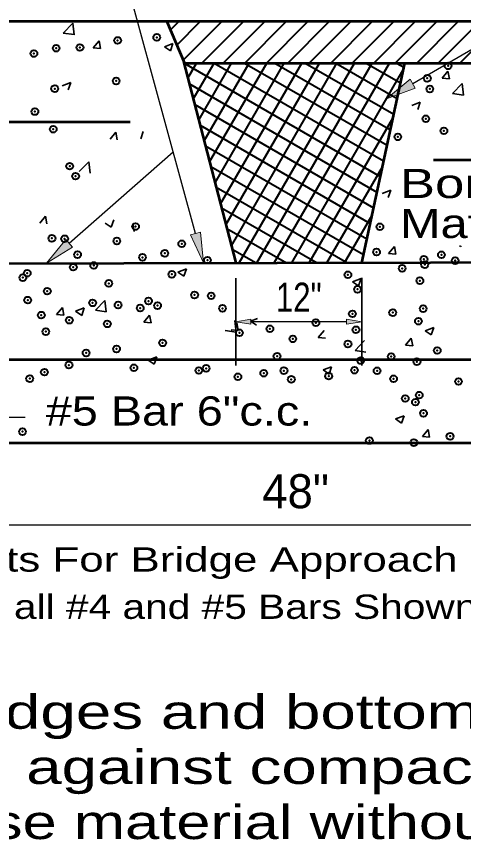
# Model space of a CAD drawing. Extents: x 36.4 to 71.7, y 0.5 to 22.5.
# Drawn here: x 46.897 to 48.735, y 6.743 to 10.127 of the extents above; entities that cross this region are included whole.
import ezdxf

# ---------------------------------------------------------------- set-up
doc = ezdxf.new("R2010")
doc.units = 0
doc.header["$LTSCALE"] = 0.056
doc.header["$PDMODE"] = 32
doc.header["$PDSIZE"] = 0.028
for name, color, linetype, lineweight in [('1', 7, 'Continuous', 40), ('3', 7, 'Continuous', 13), ('6', 7, 'Continuous', 13)]:
    doc.layers.add(name, color=color, linetype=linetype, lineweight=lineweight)

msp = doc.modelspace()

# ---------------------------------------------------------------- hatches: boundary and pattern name
at = {"layer": '1'}
for points in [[(47.86117, 8.86158), (47.86117, 8.88242), (47.79867, 8.872), (47.79867, 8.872)], [(48.25425, 8.86158), (48.25425, 8.88242), (48.31675, 8.872), (48.31675, 8.872)]]:
    msp.add_hatch(color=256, dxfattribs=at).paths.add_polyline_path(points)
at = {"layer": '3'}
for points in [[(48.53658, 9.83267), (48.51558, 9.86858), (48.41808, 9.78783), (48.41808, 9.78783)], [(47.65308, 9.23942), (47.61283, 9.2285), (47.66592, 9.11342), (47.66592, 9.11342)], [(47.12742, 9.17892), (47.09992, 9.21025), (47.01983, 9.11208), (47.01983, 9.11208)]]:
    msp.add_hatch(color=256, dxfattribs=at).paths.add_polyline_path(points)

# ---------------------------------------------------------------- linework, layer by layer
at = {"layer": '1', "lineweight": 35}
for p, q in [((47.089, 10.05883), (47.128, 10.09942)), ((47.1335, 10.05192), (47.128, 10.09942)), ((47.089, 10.05883), (47.1335, 10.052)), ((47.21225, 9.99808), (47.23633, 10.02683)), ((47.24217, 9.9955), (47.23633, 10.02683)), ((47.50517, 10.00258), (47.54017, 10.01608)), ((47.53008, 9.98583), (47.54017, 10.01608)), ((47.21225, 9.99808), (47.24217, 9.9955)), ((47.50517, 10.00258), (47.53008, 9.98583)), ((47.57083, 9.96675), (47.57317, 9.96942)), ((47.57083, 9.96675), (47.57442, 9.96642)), ((48.64675, 9.87258), (48.67083, 9.90133)), ((48.67667, 9.87), (48.67083, 9.90133)), ((47.08508, 9.84133), (47.12008, 9.85475)), ((47.10992, 9.82458), (47.12008, 9.85475)), ((48.64675, 9.87258), (48.67667, 9.87)), ((48.68992, 9.81058), (48.72883, 9.85117)), ((48.73433, 9.80367), (48.72883, 9.85117)), ((48.68992, 9.81058), (48.73433, 9.80367)), ((48.52217, 9.76125), (48.55717, 9.77467)), ((48.54708, 9.7445), (48.55725, 9.77467)), ((47.28158, 9.622), (47.30575, 9.65075)), ((47.3115, 9.61942), (47.30575, 9.65075)), ((47.40842, 9.62325), (47.4185, 9.6535)), ((47.15533, 9.48908), (47.19425, 9.52967)), ((47.15533, 9.48908), (47.19425, 9.52967)), ((47.19983, 9.48217), (47.19425, 9.52958)), ((48.4005, 9.39867), (48.43558, 9.41208)), ((48.42542, 9.38192), (48.43558, 9.41208)), ((46.99233, 9.27725), (47.0165, 9.306)), ((47.02225, 9.27467), (47.0165, 9.306)), ((47.26183, 9.2775), (47.28675, 9.26067)), ((47.28675, 9.26067), (47.29692, 9.29092)), ((47.38092, 9.24325), (47.37508, 9.27458)), ((48.42692, 9.15175), (48.451, 9.1805)), ((48.45675, 9.14917), (48.451, 9.1805)), ((48.71817, 9.18442), (48.72383, 9.18058)), ((48.72383, 9.18058), (48.72517, 9.18442)), ((48.42692, 9.15175), (48.45675, 9.14917)), ((47.56033, 9.07617), (47.59533, 9.08958)), ((47.56033, 9.07617), (47.58517, 9.05942)), ((47.58517, 9.05933), (47.59533, 9.08958)), ((47.79867, 9.05125), (47.79867, 8.692)), ((48.27892, 9.03608), (48.31392, 9.04958)), ((48.27892, 9.03608), (48.30375, 9.01933)), ((48.30375, 9.01933), (48.31392, 9.0495)), ((48.31675, 9.05233), (48.31675, 8.692)), ((47.22158, 8.91925), (47.26058, 8.95983)), ((47.26608, 8.91233), (47.26058, 8.95983)), ((47.06175, 8.90117), (47.08583, 8.92992)), ((47.06175, 8.90117), (47.09158, 8.89858)), ((47.09167, 8.89858), (47.08583, 8.92992)), ((47.14017, 8.91492), (47.17525, 8.92833)), ((47.14017, 8.91492), (47.16508, 8.89808)), ((47.16508, 8.89808), (47.17525, 8.92833)), ((47.22158, 8.91925), (47.26608, 8.91233)), ((47.42033, 8.86983), (47.4445, 8.8985)), ((47.42033, 8.86983), (47.45025, 8.86717)), ((47.45025, 8.86717), (47.4445, 8.8985)), ((47.79967, 8.82958), (47.79417, 8.87708)), ((47.80892, 8.83583), (47.80308, 8.86717)), ((47.85875, 8.87483), (47.8875, 8.88583)), ((47.85875, 8.87483), (47.88367, 8.85808)), ((47.75525, 8.8365), (47.79967, 8.82958)), ((47.779, 8.83842), (47.80892, 8.83583)), ((48.13767, 8.80708), (48.16175, 8.83575)), ((48.57733, 8.83483), (48.61233, 8.84825)), ((48.57733, 8.83483), (48.60217, 8.818)), ((48.60225, 8.818), (48.61233, 8.84825)), ((48.13767, 8.80708), (48.1675, 8.80442)), ((48.49625, 8.77567), (48.52033, 8.80442)), ((48.52617, 8.77308), (48.52033, 8.80442)), ((48.28883, 8.75367), (48.32783, 8.79433)), ((48.49625, 8.77567), (48.52617, 8.77308)), ((48.28883, 8.75367), (48.33333, 8.74683)), ((47.43867, 8.71358), (47.47367, 8.727)), ((47.43867, 8.71358), (47.4635, 8.69683)), ((47.4635, 8.69683), (47.47367, 8.727)), ((48.15725, 8.6735), (48.19225, 8.687)), ((48.15725, 8.6735), (48.18208, 8.65675)), ((48.18208, 8.65675), (48.19225, 8.687)), ((48.45567, 8.47225), (48.49067, 8.48567)), ((48.45567, 8.47225), (48.48058, 8.45542)), ((48.48058, 8.45542), (48.49067, 8.48567)), ((48.56567, 8.39958), (48.58975, 8.42833)), ((48.5955, 8.39692), (48.58975, 8.42833)), ((48.56567, 8.39958), (48.5955, 8.397))]:
    msp.add_line(p, q, dxfattribs=at)
at = {"layer": '1', "lineweight": 53}
for p, q in [((53.64358, 10.10608), (47.51525, 10.10608)), ((47.51525, 10.10608), (47.58758, 9.9355)), ((47.5825, 9.94733), (47.79867, 9.11375)), ((47.58758, 9.9355), (53.64358, 9.9355)), ((48.3165, 9.11375), (48.493, 9.9355)), ((47.36392, 9.69192), (43.57042, 9.69192)), ((52.62333, 9.53608), (48.61192, 9.53608)), ((49.75083, 8.71517), (46.304, 8.71517)), ((50.03808, 8.37225), (46.07633, 8.37225))]:
    msp.add_line(p, q, dxfattribs=at)
at = {"layer": '1'}
for p, q in [((47.52992, 10.0715), (47.5645, 10.10608)), ((47.55625, 10.00942), (47.65283, 10.10608)), ((47.5825, 9.94733), (47.74125, 10.10608)), ((47.65908, 9.9355), (47.82967, 10.10608)), ((47.74742, 9.9355), (47.918, 10.10608)), ((47.83583, 9.9355), (48.00642, 10.10608)), ((47.92425, 9.9355), (48.09483, 10.10608)), ((48.01258, 9.9355), (48.18317, 10.10608)), ((48.101, 9.9355), (48.27158, 10.10608)), ((48.18942, 9.9355), (48.36, 10.10608)), ((48.27775, 9.9355), (48.44833, 10.10608)), ((48.36617, 9.9355), (48.53675, 10.10608)), ((48.45458, 9.9355), (48.62517, 10.10608)), ((48.54292, 9.9355), (48.7135, 10.10608)), ((48.63133, 9.9355), (48.80192, 10.10608)), ((48.71975, 9.9355), (48.89033, 10.10608)), ((47.58583, 9.93467), (48.39275, 9.46883)), ((47.60158, 9.87375), (47.63725, 9.9355)), ((47.624, 9.78742), (47.70942, 9.9355)), ((47.64633, 9.70117), (47.78158, 9.9355)), ((47.66867, 9.61492), (47.85375, 9.9355)), ((47.69108, 9.52867), (47.92592, 9.9355)), ((47.7095, 9.9355), (48.40658, 9.533)), ((47.71342, 9.44242), (47.99808, 9.9355)), ((47.73583, 9.35617), (48.07025, 9.9355)), ((47.75817, 9.26983), (48.14242, 9.9355)), ((47.7805, 9.18358), (48.21458, 9.9355)), ((47.81233, 9.11375), (48.28675, 9.9355)), ((47.8345, 9.9355), (48.42033, 9.59725)), ((47.8845, 9.11375), (48.35892, 9.9355)), ((47.95667, 9.11375), (48.43108, 9.9355)), ((47.9595, 9.9355), (48.43417, 9.66142)), ((48.0845, 9.9355), (48.44792, 9.72558)), ((48.2095, 9.9355), (48.46175, 9.78983)), ((48.3345, 9.9355), (48.4755, 9.854)), ((48.4595, 9.9355), (48.48933, 9.91825)), ((48.02883, 9.11375), (48.48692, 9.90717)), ((47.60783, 9.84983), (48.379, 9.40458)), ((47.62983, 9.765), (48.36517, 9.34042)), ((47.65183, 9.68008), (48.35142, 9.27617)), ((48.101, 9.11375), (48.44417, 9.70808)), ((47.67383, 9.59525), (48.33758, 9.212)), ((47.69583, 9.51033), (48.32383, 9.14775)), ((48.17317, 9.11375), (48.40142, 9.509)), ((47.71783, 9.4255), (48.25775, 9.11375)), ((47.73983, 9.34058), (48.13275, 9.11375)), ((48.24533, 9.11375), (48.35867, 9.30992)), ((47.76183, 9.25575), (48.00775, 9.11375)), ((47.78383, 9.17083), (47.88275, 9.11375))]:
    msp.add_line(p, q, dxfattribs=at)
at = {"layer": '1', "lineweight": 25}
for p, q in [((48.25425, 8.872), (47.86117, 8.872)), ((49.91308, 8.03517), (46.20133, 8.03517))]:
    msp.add_line(p, q, dxfattribs=at)
at = {"layer": '1', "lineweight": 53}
msp.add_lwpolyline([(47.51525, 10.10608), (43.59017, 10.10608), (43.59017, 9.827), (43.43175, 9.55683), (43.67933, 9.42175), (43.62983, 9.27633), (44.10525, 9.27633), (46.07633, 9.11), (53.64175, 9.12625)], dxfattribs=at)
at = {"layer": '1', "lineweight": 13}
for points in [[(47.86117, 8.86158), (47.86117, 8.88242), (47.79867, 8.872), (47.79867, 8.872)], [(48.25425, 8.86158), (48.25425, 8.88242), (48.31675, 8.872), (48.31675, 8.872)]]:
    msp.add_lwpolyline(points, close=True, dxfattribs=at)
at = {"layer": '1'}
for p in [(47.47367, 10.04083), (47.31283, 10.02817), (46.9685, 9.97433), (47.06025, 9.99617), (47.15792, 9.99925), (48.6715, 9.92358), (48.586, 9.87275), (47.30675, 9.86175), (47.05417, 9.82975), (48.59642, 9.82892), (46.97267, 9.73575), (48.57992, 9.70625), (47.04808, 9.66333), (48.46483, 9.63167), (48.65425, 9.65658), (47.11567, 9.51133), (47.14017, 9.47033), (47.38658, 9.26308), (48.39117, 9.26217), (47.04275, 9.21483), (47.095, 9.213), (47.30967, 9.20358), (47.57658, 9.19225), (48.37733, 9.15842), (47.14817, 9.14767), (47.41508, 9.13642), (47.50642, 9.15325), (47.682, 9.12508), (48.57217, 9.1285), (48.64425, 9.14717), (48.70058, 9.12308), (47.1305, 9.09625), (47.21483, 9.10325), (48.48275, 9.09125), (48.57542, 9.10658), (46.94117, 9.07133), (47.536, 9.067), (48.25958, 9.065), (46.92325, 9.05317), (47.27633, 9.0295), (48.55558, 9.0405), (47.02375, 8.9975), (48.29892, 9.00525), (46.94325, 8.96067), (47.43992, 8.95708), (47.62933, 8.982), (47.69733, 8.97833), (47.21017, 8.94942), (47.31475, 8.94058), (47.40575, 8.92825), (47.47708, 8.93808), (47.744, 8.92683), (48.569, 8.92583), (46.999, 8.899), (48.27783, 8.90425), (48.44383, 8.90933), (47.11417, 8.87817), (47.27025, 8.86308), (48.12808, 8.86775), (48.5495, 8.874), (47.01767, 8.83108), (47.81358, 8.82642), (47.93875, 8.84283), (48.29283, 8.83883), (47.49775, 8.78483), (48.03308, 8.80133), (47.30842, 8.75992), (48.25992, 8.78008), (48.62683, 8.75358), (47.18325, 8.74342), (47.96833, 8.73), (48.4375, 8.72867), (47.11283, 8.69392), (47.37975, 8.68258), (48.31233, 8.71217), (48.54342, 8.70758), (47.01158, 8.66458), (47.64667, 8.67133), (47.67675, 8.68), (47.91358, 8.66008), (47.99658, 8.67058), (48.1805, 8.64875), (48.28675, 8.67242), (48.37967, 8.67033), (46.95133, 8.638), (47.80717, 8.64567), (48.027, 8.63492), (48.44742, 8.6375), (48.71433, 8.62625), (48.49533, 8.55633), (48.55283, 8.57033), (48.53733, 8.54117), (48.57067, 8.49533), (46.92175, 8.42), (48.34792, 8.38333), (48.67958, 8.40075), (48.53125, 8.37467)]:
    msp.add_point(p, dxfattribs=at)
at = {"layer": '3', "lineweight": 25}
for p, q in [((48.52608, 9.85067), (50.90675, 11.2355)), ((47.11375, 9.19458), (47.54125, 9.57008))]:
    msp.add_line(p, q, dxfattribs=at)
for points in [[(47.633, 9.234), (47.23175, 10.70433), (46.89858, 10.70433)], [(46.52567, 8.63), (46.68658, 8.48008), (46.93275, 8.48008)]]:
    msp.add_lwpolyline(points, dxfattribs=at)
at = {"layer": '3'}
for points in [[(48.53658, 9.83267), (48.51558, 9.86858), (48.41808, 9.78783), (48.41808, 9.78783)], [(47.65308, 9.23942), (47.61283, 9.2285), (47.66592, 9.11342), (47.66592, 9.11342)], [(47.12742, 9.17892), (47.09992, 9.21025), (47.01983, 9.11208), (47.01983, 9.11208)]]:
    msp.add_lwpolyline(points, close=True, dxfattribs=at)
at = {"layer": '6'}
for p, q in [((47.51525, 10.10608), (47.51533, 10.10608)), ((47.51525, 10.10608), (47.51533, 10.10608)), ((47.79867, 9.11375), (47.79875, 9.11375)), ((48.31675, 9.11483), (48.31683, 9.11483)), ((47.79867, 8.872), (47.79875, 8.872))]:
    msp.add_line(p, q, dxfattribs=at)

# ---------------------------------------------------------------- texts
at = {"layer": '1'}
msp.add_text('48"', height=0.14, dxfattribs=at).set_placement((47.90725, 8.10517))
at = {"layer": '3'}
for s, height, width, p in [('Bond Breaking', 0.12, 1.35, (48.47325, 9.38017)), ('Material', 0.12, 1.25, (48.47325, 9.21592)), ('12"', 0.12, 0.8, (47.96342, 8.91258)), ('#5 Bar 6"c.c.', 0.12, 1.2, (47.01725, 8.445)), ('Pay Limits For Bridge Approach Expansion Joint', 0.1, 1.35, (46.16208, 7.84458)), ('(Includes all #4 and #5 Bars Shown above)', 0.1, 1.25, (46.16208, 7.65033)), ('Outside edges and bottom of subslab', 0.14, 1.4, (45.72758, 7.1985)), ('to be cast against compacted subgrade', 0.14, 1.4, (45.72758, 6.97183)), ('and/or base material without forms.', 0.14, 1.35, (45.72758, 6.74517))]:
    msp.add_text(s, height=height, dxfattribs=dict(at, width=width)).set_placement(p)

doc.saveas('drawing.dxf')
